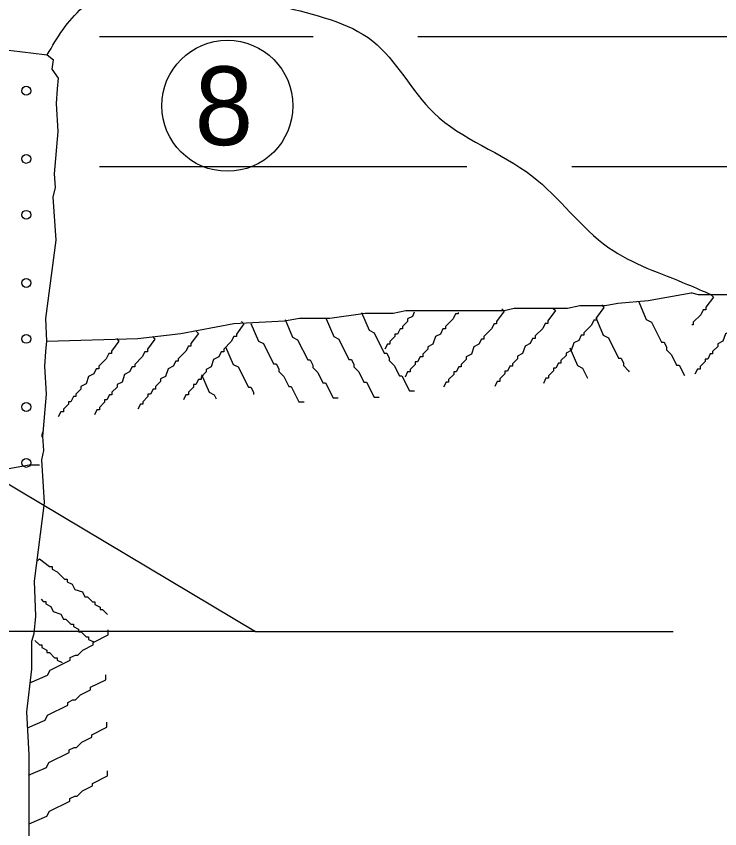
# Model space of a CAD drawing. Extents: x 49991.4 to 50021, y 49987.6 to 50011.4.
# Drawn here: x 50013.896 to 50014.432, y 50005.434 to 50006.053 of the extents above; entities that cross this region are included whole.
import ezdxf

# ---------------------------------------------------------------- set-up
doc = ezdxf.new("R2010")
doc.units = 0
for name, color, linetype in [('Level 1', 7, 'Continuous'), ('Level 2', 7, 'Continuous'), ('Level 3', 7, 'Continuous')]:
    doc.layers.add(name, color=color, linetype=linetype)

msp = doc.modelspace()

# ---------------------------------------------------------------- linework, layer by layer
at = {"layer": 'Level 1'}
for p, q in [((50014.12212, 50006.03762), (50013.95923, 50006.03762)), ((50015.73423, 50006.03762), (50014.20212, 50006.03762)), ((50013.91923, 50006.02398), (50013.92398, 50006.02025)), ((50014.23949, 50005.93862), (50013.95923, 50005.93862)), ((50015.73423, 50005.93862), (50014.31949, 50005.93862))]:
    msp.add_line(p, q, dxfattribs=at)
for points in [[(50013.92786, 50006.00609), (50013.92298, 50006.01303), (50013.92398, 50006.02025)], [(50013.919, 50005.80574), (50013.91826, 50005.82294), (50013.92594, 50005.88269), (50013.92387, 50005.91548), (50013.92547, 50005.9227), (50013.92467, 50005.93337), (50013.9276, 50005.9656), (50013.92627, 50005.98682), (50013.92707, 50005.99814), (50013.92786, 50006.00609)], [(50013.919, 50005.80574), (50013.98836, 50005.80772), (50014.02121, 50005.81154), (50014.06166, 50005.81922), (50014.10023, 50005.82118), (50014.1118, 50005.82312), (50014.13488, 50005.82312), (50014.16191, 50005.82694), (50014.1831, 50005.82694), (50014.19278, 50005.8289), (50014.23709, 50005.8289), (50014.26794, 50005.8289), (50014.27566, 50005.8308), (50014.31615, 50005.8308), (50014.32575, 50005.83276), (50014.34506, 50005.83276), (50014.3547, 50005.83467), (50014.37783, 50005.83659), (50014.4106, 50005.84239), (50014.41116, 50005.84239)], [(50014.41116, 50005.84239), (50014.41595, 50005.84118), (50014.45648, 50005.84118)], [(50014.42562, 50005.84119), (50014.42756, 50005.83927), (50014.42176, 50005.83155), (50014.42176, 50005.82963), (50014.41984, 50005.82963), (50014.4179, 50005.82576), (50014.41212, 50005.82002), (50014.41212, 50005.81804), (50014.41116, 50005.81804)], [(50014.45792, 50005.84022), (50014.45984, 50005.83832), (50014.45403, 50005.8306), (50014.45403, 50005.82864), (50014.45215, 50005.82864), (50014.45019, 50005.82481), (50014.44443, 50005.81903), (50014.44443, 50005.81709), (50014.44251, 50005.81709), (50014.44057, 50005.81323), (50014.43671, 50005.81131), (50014.43475, 50005.80551), (50014.43089, 50005.80359), (50014.43089, 50005.80165), (50014.42703, 50005.79779), (50014.42703, 50005.79587), (50014.42513, 50005.79587), (50014.42325, 50005.79201), (50014.42127, 50005.79201), (50014.42127, 50005.79006), (50014.4174, 50005.78624), (50014.4174, 50005.78428), (50014.41548, 50005.78428), (50014.41354, 50005.78046)], [(50014.34219, 50005.83322), (50014.34411, 50005.8313), (50014.33833, 50005.82358), (50014.33833, 50005.82168), (50014.33639, 50005.82168), (50014.33447, 50005.81778), (50014.32866, 50005.81199), (50014.32866, 50005.81009), (50014.32674, 50005.81009), (50014.3248, 50005.80623), (50014.32098, 50005.80427), (50014.31902, 50005.79853), (50014.31516, 50005.79659), (50014.31516, 50005.79467), (50014.3113, 50005.79081), (50014.3113, 50005.78891), (50014.30942, 50005.78891), (50014.30744, 50005.78505), (50014.30556, 50005.78505), (50014.30556, 50005.78309), (50014.30168, 50005.77923), (50014.30168, 50005.77732), (50014.29976, 50005.77732), (50014.29784, 50005.77342)], [(50014.3706, 50005.83564), (50014.37642, 50005.82213), (50014.38024, 50005.82021), (50014.38797, 50005.80477), (50014.38991, 50005.80477), (50014.39179, 50005.80095), (50014.39179, 50005.79901), (50014.39569, 50005.79514), (50014.39951, 50005.78744), (50014.40147, 50005.78744), (50014.40549, 50005.77932)], [(50014.15902, 50005.82744), (50014.16482, 50005.81395), (50014.16864, 50005.81199), (50014.17636, 50005.79659), (50014.17832, 50005.79659), (50014.18022, 50005.79273), (50014.18022, 50005.79081), (50014.18409, 50005.78695), (50014.18795, 50005.77923), (50014.18987, 50005.77923), (50014.19567, 50005.76764), (50014.19951, 50005.76764)], [(50014.19913, 50005.82777), (50014.19808, 50005.82455), (50014.19418, 50005.82263), (50014.19418, 50005.82071), (50014.19036, 50005.81685), (50014.19036, 50005.8149), (50014.18844, 50005.8149), (50014.18646, 50005.81108), (50014.18456, 50005.81108), (50014.18456, 50005.80912), (50014.18072, 50005.80526), (50014.18072, 50005.80336), (50014.17878, 50005.80336), (50014.17686, 50005.7995)], [(50014.23277, 50005.82748), (50014.23277, 50005.82649), (50014.23085, 50005.82649), (50014.22891, 50005.82263), (50014.22309, 50005.81685), (50014.22309, 50005.8149), (50014.22119, 50005.8149), (50014.21923, 50005.81108), (50014.21541, 50005.80912), (50014.21349, 50005.80336), (50014.20963, 50005.8014), (50014.20963, 50005.7995), (50014.20577, 50005.79564), (50014.20577, 50005.79368), (50014.20383, 50005.79368), (50014.20191, 50005.78982), (50014.19996, 50005.78982), (50014.19996, 50005.78792), (50014.19614, 50005.78408), (50014.19614, 50005.78214), (50014.19418, 50005.78214), (50014.1923, 50005.77824)], [(50014.26606, 50005.83031), (50014.26794, 50005.82841), (50014.26218, 50005.82071), (50014.26218, 50005.81877), (50014.26022, 50005.81877), (50014.25832, 50005.8149), (50014.25253, 50005.80912), (50014.25253, 50005.80722), (50014.25061, 50005.80722), (50014.24863, 50005.80336), (50014.24481, 50005.8014), (50014.24289, 50005.79564), (50014.23903, 50005.79368), (50014.23903, 50005.79174), (50014.23517, 50005.78792), (50014.23517, 50005.786), (50014.23327, 50005.786), (50014.23131, 50005.78214), (50014.22941, 50005.78214), (50014.22941, 50005.78022), (50014.22555, 50005.77633), (50014.22555, 50005.77441), (50014.22359, 50005.77441), (50014.22171, 50005.77055)], [(50014.30506, 50005.8308), (50014.30698, 50005.8289), (50014.3012, 50005.82118), (50014.3012, 50005.81922), (50014.2993, 50005.81922), (50014.29734, 50005.81536), (50014.29158, 50005.80962), (50014.29158, 50005.80772), (50014.28962, 50005.80772), (50014.28772, 50005.80382), (50014.28386, 50005.8019), (50014.28194, 50005.79613), (50014.27808, 50005.79417), (50014.27808, 50005.79227), (50014.27421, 50005.78843), (50014.27421, 50005.78645), (50014.27227, 50005.78645), (50014.27035, 50005.78263), (50014.26843, 50005.78263), (50014.26843, 50005.78069), (50014.26457, 50005.77685), (50014.26457, 50005.77491), (50014.26267, 50005.77491), (50014.26071, 50005.77101)], [(50014.06744, 50005.82071), (50014.06934, 50005.81877), (50014.06358, 50005.81108), (50014.06358, 50005.8091), (50014.06166, 50005.8091), (50014.05972, 50005.80526), (50014.05398, 50005.7995), (50014.05398, 50005.79754), (50014.05202, 50005.79754), (50014.05008, 50005.79368), (50014.04622, 50005.79174), (50014.0443, 50005.78596), (50014.04048, 50005.78408), (50014.04048, 50005.78214), (50014.03658, 50005.77824), (50014.03658, 50005.77633), (50014.03467, 50005.77633), (50014.03271, 50005.77249), (50014.03081, 50005.77249), (50014.03081, 50005.77055), (50014.02695, 50005.76669), (50014.02695, 50005.76477), (50014.02503, 50005.76477), (50014.02311, 50005.76091)], [(50014.07469, 50005.81922), (50014.08043, 50005.80574), (50014.08429, 50005.80382), (50014.09202, 50005.78843), (50014.09398, 50005.78843), (50014.09588, 50005.78455), (50014.09588, 50005.78259), (50014.09974, 50005.77873), (50014.1036, 50005.77101), (50014.10548, 50005.77101), (50014.11126, 50005.75946), (50014.11518, 50005.75946)], [(50014.10071, 50005.82213), (50014.10647, 50005.80863), (50014.11033, 50005.80669), (50014.11805, 50005.79128), (50014.11997, 50005.79128), (50014.12191, 50005.78744), (50014.12191, 50005.78546), (50014.12577, 50005.78164), (50014.12964, 50005.77392), (50014.13156, 50005.77392), (50014.13736, 50005.76238), (50014.14122, 50005.76238)], [(50014.13201, 50005.82259), (50014.13783, 50005.8091), (50014.14165, 50005.80718), (50014.14942, 50005.79174), (50014.15132, 50005.79174), (50014.15324, 50005.78792), (50014.15324, 50005.78596), (50014.1571, 50005.78214), (50014.16096, 50005.77437), (50014.1629, 50005.77437), (50014.16864, 50005.76287), (50014.1725, 50005.76287)], [(50014.33783, 50005.82358), (50014.34357, 50005.81009), (50014.34747, 50005.80813), (50014.3552, 50005.79269), (50014.35714, 50005.79269), (50014.35902, 50005.78887), (50014.35902, 50005.78695), (50014.36288, 50005.78309), (50014.36337, 50005.78214)], [(50014.03271, 50005.81348), (50014.03467, 50005.81154), (50014.02885, 50005.80382), (50014.02885, 50005.8019), (50014.02695, 50005.8019), (50014.02503, 50005.79804), (50014.01925, 50005.79227), (50014.01925, 50005.79031), (50014.01731, 50005.79031), (50014.01539, 50005.78645), (50014.01153, 50005.78455), (50014.00959, 50005.77873), (50014.00577, 50005.77683), (50014.00577, 50005.77491), (50014.00191, 50005.77101), (50014.00191, 50005.76913), (50013.99995, 50005.76913), (50013.99804, 50005.76527), (50013.99608, 50005.76527), (50013.99608, 50005.76333), (50013.99226, 50005.75946), (50013.99226, 50005.75754), (50013.99034, 50005.75754), (50013.98836, 50005.75368)], [(50013.97203, 50005.80772), (50013.97395, 50005.80574), (50013.96817, 50005.79804), (50013.96817, 50005.79609), (50013.96627, 50005.79609), (50013.96431, 50005.79227), (50013.9585, 50005.78645), (50013.9585, 50005.78455), (50013.95658, 50005.78455), (50013.95468, 50005.78069), (50013.95084, 50005.77873), (50013.9489, 50005.77297), (50013.945, 50005.77101), (50013.945, 50005.76913), (50013.94118, 50005.76527), (50013.94118, 50005.76333), (50013.93924, 50005.76333), (50013.93732, 50005.75946), (50013.9354, 50005.75946), (50013.9354, 50005.75754), (50013.93154, 50005.75368), (50013.93154, 50005.75178), (50013.9296, 50005.75178), (50013.92768, 50005.74788)], [(50013.99949, 50005.8091), (50014.00143, 50005.80718), (50013.99563, 50005.79946), (50013.99563, 50005.79754), (50013.99371, 50005.79754), (50013.99177, 50005.79368), (50013.98599, 50005.78792), (50013.98599, 50005.78596), (50013.98405, 50005.78596), (50013.98213, 50005.78214), (50013.97826, 50005.78022), (50013.97636, 50005.77437), (50013.9725, 50005.77247), (50013.9725, 50005.77055), (50013.96866, 50005.76669), (50013.96866, 50005.76477), (50013.96668, 50005.76477), (50013.9648, 50005.76091), (50013.96282, 50005.76091), (50013.96282, 50005.75897), (50013.959, 50005.75515), (50013.959, 50005.75319), (50013.95708, 50005.75319), (50013.95518, 50005.74933)], [(50013.91056, 50005.59582), (50013.9094, 50005.62259), (50013.91708, 50005.68234), (50013.91501, 50005.71513), (50013.91661, 50005.72235), (50013.91581, 50005.73302), (50013.91874, 50005.76525), (50013.91741, 50005.78647), (50013.91821, 50005.79779), (50013.919, 50005.80574)], [(50014.05539, 50005.8014), (50014.06121, 50005.78792), (50014.06503, 50005.78596), (50014.07279, 50005.77055), (50014.07469, 50005.77055), (50014.07661, 50005.76669), (50014.07661, 50005.76505)], [(50014.31803, 50005.80041), (50014.32387, 50005.78695), (50014.32771, 50005.78501), (50014.33158, 50005.77732)], [(50014.03707, 50005.78022), (50014.04285, 50005.76669), (50014.04675, 50005.76477), (50014.04826, 50005.7617)], [(50013.50839, 50005.71249), (50013.51345, 50005.71296), (50013.52371, 50005.71249), (50013.57779, 50005.71236), (50013.59728, 50005.71143), (50013.62047, 50005.71262), (50013.64779, 50005.71089), (50013.67325, 50005.71316), (50013.69071, 50005.71063), (50013.69857, 50005.71116), (50013.70337, 50005.71209), (50013.7091, 50005.71249), (50013.74361, 50005.71131), (50013.80337, 50005.71422), (50013.8342, 50005.71368), (50013.85099, 50005.7124), (50013.87084, 50005.7099), (50013.88431, 50005.70745), (50013.90554, 50005.71131), (50013.91324, 50005.71131)], [(50013.91132, 50005.63753), (50013.91328, 50005.63949), (50013.92096, 50005.63367), (50013.92288, 50005.63367), (50013.92288, 50005.63176), (50013.92674, 50005.6298), (50013.93251, 50005.62404), (50013.93447, 50005.62404), (50013.93447, 50005.62212), (50013.93829, 50005.62018), (50013.94021, 50005.61632), (50013.94605, 50005.61436), (50013.94795, 50005.61054), (50013.94987, 50005.61054), (50013.95377, 50005.60672), (50013.95565, 50005.60672), (50013.95565, 50005.60476), (50013.95951, 50005.60282), (50013.95951, 50005.6009), (50013.96145, 50005.6009), (50013.96532, 50005.59702)], [(50013.91453, 50005.60872), (50013.91613, 50005.60714), (50013.91805, 50005.60714), (50013.91805, 50005.6052), (50013.92187, 50005.60328), (50013.92385, 50005.59946), (50013.92964, 50005.59748), (50013.93156, 50005.59364), (50013.9335, 50005.59364), (50013.93736, 50005.58978), (50013.93928, 50005.58978), (50013.93928, 50005.58788), (50013.9431, 50005.58592), (50013.9431, 50005.58401), (50013.94504, 50005.58401), (50013.9489, 50005.58015), (50013.95082, 50005.58015), (50013.95082, 50005.57819), (50013.95472, 50005.57629)], [(50013.90554, 50005.42449), (50013.90554, 50005.48422), (50013.90554, 50005.49002), (50013.90364, 50005.52283), (50013.90746, 50005.55556), (50013.90746, 50005.57679), (50013.90938, 50005.58253), (50013.91056, 50005.59582)], [(50013.90601, 50005.54497), (50013.91954, 50005.55075), (50013.92146, 50005.55463), (50013.93686, 50005.56233), (50013.93686, 50005.56423), (50013.94068, 50005.56619), (50013.94266, 50005.56619), (50013.94652, 50005.57006), (50013.95423, 50005.57392), (50013.95423, 50005.5758), (50013.96581, 50005.5816), (50013.96581, 50005.58546)], [(50013.90978, 50005.57738), (50013.91326, 50005.57392), (50013.91518, 50005.57392), (50013.91518, 50005.57194), (50013.919, 50005.57006), (50013.919, 50005.5681), (50013.92096, 50005.5681), (50013.92478, 50005.56421), (50013.92672, 50005.56421), (50013.92672, 50005.56233), (50013.93059, 50005.56041)], [(50013.90413, 50005.51075), (50013.9176, 50005.51652), (50013.91954, 50005.52038), (50013.93492, 50005.5281), (50013.93492, 50005.53002), (50013.93878, 50005.53194), (50013.94068, 50005.53194), (50013.94458, 50005.53582), (50013.95231, 50005.53966), (50013.95231, 50005.54164), (50013.96385, 50005.54738), (50013.96385, 50005.55125)], [(50013.90504, 50005.47458), (50013.91855, 50005.48036), (50013.92047, 50005.48424), (50013.93591, 50005.49194), (50013.93591, 50005.49388), (50013.93977, 50005.49581), (50013.94167, 50005.49581), (50013.94553, 50005.49967), (50013.95326, 50005.50353), (50013.95326, 50005.50543), (50013.96482, 50005.51125), (50013.96482, 50005.51511)], [(50013.90554, 50005.43749), (50013.91904, 50005.44326), (50013.92096, 50005.44712), (50013.93641, 50005.45482), (50013.93641, 50005.4568), (50013.94027, 50005.45868), (50013.94217, 50005.45868), (50013.94603, 50005.46254), (50013.95375, 50005.4664), (50013.95375, 50005.46834), (50013.96532, 50005.47412), (50013.96532, 50005.47799)]]:
    msp.add_lwpolyline(points, dxfattribs=at)
for centre in [(50013.90321, 50005.99659), (50013.90321, 50005.94466), (50013.90321, 50005.90199), (50013.90321, 50005.85006), (50013.90321, 50005.80739), (50013.90321, 50005.75546), (50013.90321, 50005.71279)]:
    msp.add_circle(centre, 0.00341, dxfattribs=at)
msp.add_arc((50013.91845, 50005.73413), 0.00341, 132.58685, 221.58606, dxfattribs=at)
msp.add_arc((50013.91845, 50005.73413), 0.00341, 132.58685, 221.58606, dxfattribs=at)
for points in [[(50013.91923, 50006.02398), (50013.94601, 50006.05982), (50014.00475, 50006.07985), (50014.0982, 50006.06116), (50014.16762, 50006.03446), (50014.21434, 50005.97972), (50014.2891, 50005.93166), (50014.34784, 50005.87693), (50014.40792, 50005.84889), (50014.42563, 50005.84118)], [(50013.45498, 50006.03762), (50013.5141, 50006.0425), (50013.56955, 50006.03557), (50013.62073, 50006.03557), (50013.75054, 50006.03077), (50013.76787, 50006.03023), (50013.82331, 50006.03557), (50013.85191, 50006.03251), (50013.91923, 50006.02398)]]:
    msp.add_spline(points, degree=3, dxfattribs=at)
at = {"layer": 'Level 2'}
msp.add_circle((50014.0567, 50005.98518), 0.05, dxfattribs=at)
at = {"layer": 'Level 3'}
for p, q in [((50013.67336, 50005.82542), (50014.0781, 50005.58418)), ((50014.0781, 50005.58418), (50013.67336, 50005.58418)), ((50014.0781, 50005.58418), (50014.39699, 50005.58418))]:
    msp.add_line(p, q, dxfattribs=at)

# ---------------------------------------------------------------- texts
at = {"layer": 'Level 2'}
msp.add_text('8', height=0.06, dxfattribs=at).set_placement((50014.03172, 50005.95518))

doc.saveas('drawing.dxf')
